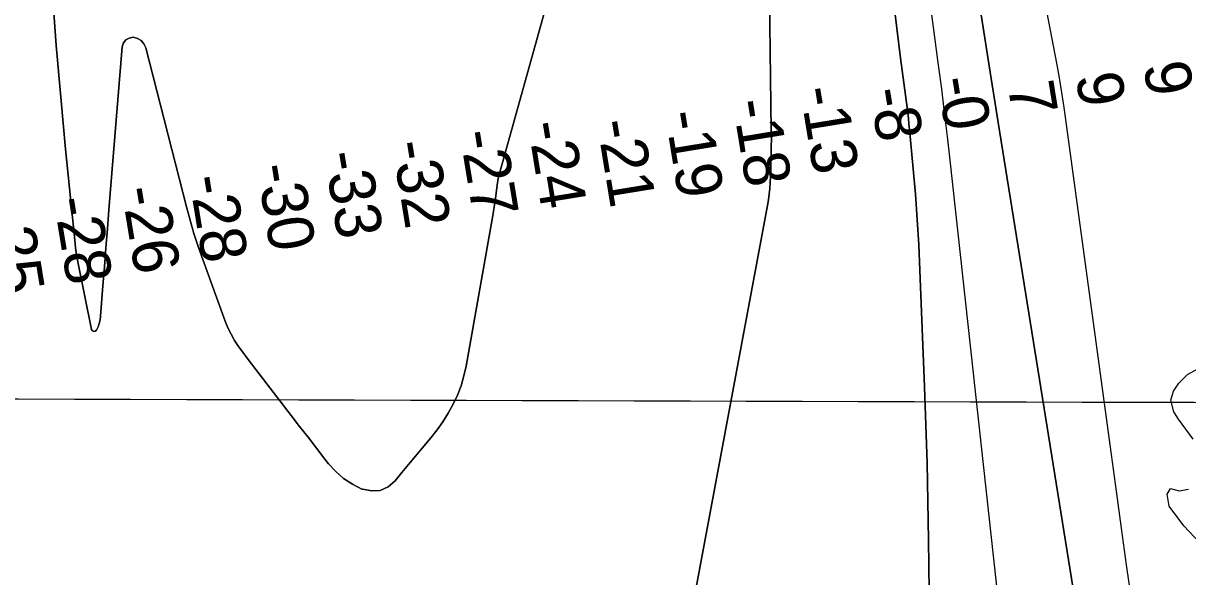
# Model space of a CAD drawing. Extents: x 3161665 to 3199565, y 885729 to 911164.
# Drawn here: x 3176516 to 3178214, y 896967 to 897774 of the extents above; entities that cross this region are included whole.
import ezdxf

# ---------------------------------------------------------------- set-up
doc = ezdxf.new("R2010")
doc.units = 0
for name, color, linetype in [('V-GRID-MAJR', 7, 'Continuous'), ('V-RIVR-EDGE', 7, 'Continuous'), ('V-RIVR-RANG', 7, 'Continuous'), ('V-TOPO-DPTH', 7, 'Continuous'), ('V-TOPO-MINR', 7, 'Continuous')]:
    doc.layers.add(name, color=color, linetype=linetype)

msp = doc.modelspace()

# ---------------------------------------------------------------- linework, layer by layer
at = {"layer": 'V-GRID-MAJR'}
msp.add_spline([(3165896.843, 897258.21), (3171121.2120000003, 897241.873), (3176345.5840000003, 897226.295), (3181569.957, 897211.478), (3186794.333, 897197.42), (3192018.711, 897184.122), (3197243.091, 897171.584), (3197243.092, 897171.584)], degree=3, dxfattribs=at)
at = {"layer": 'V-RIVR-EDGE'}
for points in [[(3178221.800052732, 897167.374816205), (3178200.571841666, 897196.116133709), (3178193.6438879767, 897207.0002441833), (3178189.3390410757, 897223.963377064), (3178193.2833747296, 897236.9939994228), (3178201.1365726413, 897248.7109187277), (3178213.339760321, 897261.7211193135), (3178271.665952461, 897293.7431551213)], [(3178231.857173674, 897015.6469121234), (3178208.4469813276, 897040.9161915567), (3178186.783018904, 897069.2239073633), (3178183.784351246, 897087.0531688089), (3178188.586214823, 897095.300199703), (3178201.617912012, 897091.790542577), (3178215.099333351, 897094.3652820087)]]:
    msp.add_lwpolyline(points, dxfattribs=at)
at = {"layer": 'V-TOPO-DPTH'}
for points in [[(3176558.5467961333, 897817.1781093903), (3176563.9325209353, 897741.495914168), (3176570.356555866, 897665.8947734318), (3176577.4727975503, 897590.3476690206), (3176591.3818922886, 897452.8044901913), (3176592.161481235, 897446.0843880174), (3176593.0721583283, 897439.3840700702), (3176594.1794676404, 897432.7134284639), (3176595.4178651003, 897426.062571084), (3176615.3516896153, 897327.1175453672), (3176616.903670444, 897325.0651113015), (3176618.605038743, 897324.033915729), (3176620.530488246, 897324.5345778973), (3176622.6053252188, 897326.0564785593), (3176624.8307228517, 897330.9478512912), (3176626.6335518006, 897335.9621829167), (3176627.802527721, 897341.1609528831), (3176628.548934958, 897346.4826817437), (3176631.9842188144, 897390.9979992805), (3176634.1354684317, 897418.671701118), (3176636.307454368, 897446.3437636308), (3176638.510544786, 897474.0133671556), (3176640.7343715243, 897501.6813313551), (3176659.9849144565, 897739.514971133), (3176662.011104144, 897745.2858974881), (3176665.1738907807, 897749.7408993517), (3176670.041572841, 897752.2220144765), (3176676.045851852, 897753.3872051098), (3176682.4314041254, 897751.6444726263), (3176687.8172042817, 897748.6977806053), (3176691.7033762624, 897743.9451492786), (3176694.5897961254, 897737.9885584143), (3176753.850988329, 897505.9194578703), (3176759.118354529, 897486.5033590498), (3176764.767142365, 897467.2050996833), (3176770.9880626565, 897448.0835994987), (3176777.590404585, 897429.0799387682), (3176810.2576448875, 897339.3855753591), (3176814.244132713, 897329.6909031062), (3176818.732541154, 897320.2607260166), (3176823.973830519, 897311.2272916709), (3176829.7170404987, 897302.4583524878), (3176835.889227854, 897293.9255698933), (3176842.123683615, 897285.4390635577), (3176848.4515419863, 897277.0219716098), (3176854.841668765, 897268.6511559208), (3176906.4900322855, 897201.7634021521), (3176918.7918004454, 897185.8541747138), (3176931.107930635, 897169.9560890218), (3176943.4456038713, 897154.0747159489), (3176955.797639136, 897138.2044846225), (3176961.084816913, 897131.4208671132), (3176971.5675435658, 897119.9552063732), (3176983.0130185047, 897109.7560533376), (3176995.9026158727, 897101.4566618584), (3177009.7549615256, 897094.4237780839), (3177010.4865470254, 897094.1220271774), (3177023.8712964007, 897091.619790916), (3177036.44042938, 897092.2990701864), (3177047.7861377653, 897097.7506227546), (3177058.316229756, 897106.3836908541), (3177068.0194433, 897118.3605052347), (3177077.7738969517, 897130.2951632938), (3177087.6052107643, 897142.1665868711), (3177097.487764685, 897153.995854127), (3177110.1230216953, 897169.0212029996), (3177119.2508104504, 897180.6517842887), (3177127.8262804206, 897192.6496344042), (3177135.573272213, 897205.1983877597), (3177142.7679452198, 897218.1144099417), (3177148.9085474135, 897231.5229973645), (3177154.2174806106, 897245.2119264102), (3177158.278910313, 897259.3213678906), (3177161.5086710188, 897273.7111509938), (3177200.5150993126, 897493.2873469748), (3177201.062739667, 897496.4032050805), (3177201.602780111, 897499.5203655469), (3177202.1314206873, 897502.639479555), (3177202.6524613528, 897505.7598959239), (3177203.148017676, 897508.8841289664), (3177203.6172047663, 897512.0121471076), (3177204.0468380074, 897515.145842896), (3177204.450102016, 897518.2833237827), (3177205.442649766, 897526.4113099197), (3177206.3350441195, 897533.6140049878), (3177207.2442922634, 897540.814541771), (3177208.1788210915, 897548.0118411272), (3177366.8356769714, 898116.712114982)], [(3177366.8356769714, 898116.712114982), (3177208.1788210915, 897548.0118411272), (3177207.2442922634, 897540.814541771), (3177206.3350441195, 897533.6140049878), (3177205.442649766, 897526.4113099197), (3177204.450102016, 897518.2833237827), (3177204.0468380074, 897515.145842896), (3177203.6172047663, 897512.0121471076), (3177203.148017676, 897508.8841289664), (3177202.6524613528, 897505.7598959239), (3177202.1314206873, 897502.639479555), (3177201.602780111, 897499.5203655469), (3177201.062739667, 897496.4032050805), (3177200.5150993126, 897493.2873469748), (3177161.5086710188, 897273.7111509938), (3177158.278910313, 897259.3213678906), (3177154.2174806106, 897245.2119264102), (3177148.9085474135, 897231.5229973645), (3177142.7679452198, 897218.1144099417), (3177135.573272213, 897205.1983877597), (3177127.8262804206, 897192.6496344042), (3177119.2508104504, 897180.6517842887), (3177110.1230216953, 897169.0212029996), (3177097.487764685, 897153.995854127), (3177087.6052107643, 897142.1665868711), (3177077.7738969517, 897130.2951632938), (3177068.0194433, 897118.3605052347), (3177058.316229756, 897106.3836908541), (3177047.7861377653, 897097.7506227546), (3177036.44042938, 897092.2990701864), (3177023.8712964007, 897091.619790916), (3177010.4865470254, 897094.1220271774), (3177009.7549615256, 897094.4237780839), (3176995.9026158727, 897101.4566618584), (3176983.0130185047, 897109.7560533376), (3176971.5675435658, 897119.9552063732), (3176961.084816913, 897131.4208671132), (3176955.797639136, 897138.2044846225), (3176943.4456038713, 897154.0747159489), (3176931.107930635, 897169.9560890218), (3176918.7918004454, 897185.8541747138), (3176906.4900322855, 897201.7634021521), (3176854.841668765, 897268.6511559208), (3176848.4515419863, 897277.0219716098), (3176842.123683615, 897285.4390635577), (3176835.889227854, 897293.9255698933), (3176829.7170404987, 897302.4583524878), (3176823.973830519, 897311.2272916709), (3176818.732541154, 897320.2607260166), (3176814.244132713, 897329.6909031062), (3176810.2576448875, 897339.3855753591), (3176777.590404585, 897429.0799387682), (3176770.9880626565, 897448.0835994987), (3176764.767142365, 897467.2050996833), (3176759.118354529, 897486.5033590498), (3176753.850988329, 897505.9194578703), (3176694.5897961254, 897737.9885584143), (3176691.7033762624, 897743.9451492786), (3176687.8172042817, 897748.6977806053), (3176682.4314041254, 897751.6444726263), (3176676.045851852, 897753.3872051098), (3176670.041572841, 897752.2220144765), (3176665.1738907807, 897749.7408993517), (3176662.011104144, 897745.2858974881), (3176659.9849144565, 897739.514971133), (3176640.7343715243, 897501.6813313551), (3176638.510544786, 897474.0133671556), (3176636.307454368, 897446.3437636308), (3176634.1354684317, 897418.671701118), (3176631.9842188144, 897390.9979992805), (3176628.548934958, 897346.4826817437), (3176627.802527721, 897341.1609528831), (3176626.6335518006, 897335.9621829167), (3176624.8307228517, 897330.9478512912), (3176622.6053252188, 897326.0564785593), (3176620.530488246, 897324.5345778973), (3176618.605038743, 897324.033915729), (3176616.903670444, 897325.0651113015), (3176615.3516896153, 897327.1175453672), (3176595.4178651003, 897426.062571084), (3176594.1794676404, 897432.7134284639), (3176593.0721583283, 897439.3840700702), (3176592.161481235, 897446.0843880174), (3176591.3818922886, 897452.8044901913), (3176577.4727975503, 897590.3476690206), (3176570.356555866, 897665.8947734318), (3176563.9325209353, 897741.495914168), (3176558.5467961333, 897817.1781093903)], [(3177494.1782761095, 896935.1771381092), (3177600.946914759, 897508.1896997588), (3177602.339676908, 897516.414515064), (3177603.5148476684, 897524.6806495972), (3177604.400248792, 897532.9868447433), (3177605.1180357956, 897541.3049577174), (3177605.5844016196, 897549.6409474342), (3177605.8831533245, 897557.9888549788), (3177606.528392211, 897589.1979617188), (3177606.6352435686, 897596.0085103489), (3177606.6968362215, 897602.8192427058), (3177606.690540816, 897609.6302506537), (3177606.6389867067, 897616.4414423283), (3177600.774823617, 898083.5755915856)], [(3177600.774823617, 898083.5755915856), (3177606.6389867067, 897616.4414423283), (3177606.690540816, 897609.6302506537), (3177606.6968362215, 897602.8192427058), (3177606.6352435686, 897596.0085103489), (3177606.528392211, 897589.1979617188), (3177605.8831533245, 897557.9888549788), (3177605.5844016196, 897549.6409474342), (3177605.1180357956, 897541.3049577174), (3177604.400248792, 897532.9868447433), (3177603.5148476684, 897524.6806495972), (3177602.339676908, 897516.414515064), (3177600.946914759, 897508.1896997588), (3177494.1782761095, 896935.1771381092)], [(3178046.6456379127, 896948.8952665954), (3177941.9240149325, 897601.6069131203), (3177937.528139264, 897629.1094230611), (3177933.153914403, 897656.6153629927), (3177928.812165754, 897684.1264479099), (3177924.4920679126, 897711.640962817), (3177904.0084826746, 897842.604480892)], [(3177904.0084826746, 897842.604480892), (3177924.4920679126, 897711.640962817), (3177928.812165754, 897684.1264479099), (3177933.153914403, 897656.6153629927), (3177937.528139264, 897629.1094230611), (3177941.9240149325, 897601.6069131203), (3178046.6456379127, 896948.8952665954)], [(3177784.425651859, 897810.8513964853), (3177789.702582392, 897766.8668961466), (3177795.2276850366, 897722.911105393), (3177804.5818895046, 897650.9532852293), (3177805.5739509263, 897642.993219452), (3177806.509894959, 897635.0268608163), (3177807.3616629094, 897627.0510628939), (3177808.1573134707, 897619.0689721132), (3177813.6078454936, 897561.2993788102), (3177816.7813359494, 897524.4074245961), (3177819.547980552, 897487.4883596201), (3177821.7043563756, 897450.5286285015), (3177823.453886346, 897413.5417866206), (3177830.0906132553, 897243.4779937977), (3177832.045480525, 897187.7502965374), (3177833.707483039, 897132.0150211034), (3177834.930188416, 897076.2683784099), (3177835.860029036, 897020.5141575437), (3177836.3474722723, 896982.241415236), (3177836.7100848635, 896945.6175398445)], [(3177784.425651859, 897810.8513964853), (3177789.702582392, 897766.8668961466), (3177795.2276850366, 897722.911105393), (3177804.5818895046, 897650.9532852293), (3177805.5739509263, 897642.993219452), (3177806.509894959, 897635.0268608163), (3177807.3616629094, 897627.0510628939), (3177808.1573134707, 897619.0689721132), (3177813.6078454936, 897561.2993788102), (3177816.7813359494, 897524.4074245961), (3177819.547980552, 897487.4883596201), (3177821.7043563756, 897450.5286285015), (3177823.453886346, 897413.5417866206), (3177830.0906132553, 897243.4779937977), (3177832.045480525, 897187.7502965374), (3177833.707483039, 897132.0150211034), (3177834.930188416, 897076.2683784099), (3177835.860029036, 897020.5141575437), (3177836.3474722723, 896982.241415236), (3177836.7100848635, 896945.6175398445)]]:
    msp.add_lwpolyline(points, dxfattribs=at)
at = {"layer": 'V-TOPO-MINR'}
for points in [[(3177976.697404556, 895952.0490213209), (3177973.571543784, 896154.3247767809), (3177971.4807912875, 896258.129303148), (3177968.741664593, 896361.9136764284), (3177965.0299766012, 896465.667820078), (3177960.6699144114, 896569.4018106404), (3177953.302895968, 896727.0636358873), (3177951.8041204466, 896755.9112628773), (3177950.104902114, 896784.7460285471), (3177948.105019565, 896813.5615022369), (3177945.904694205, 896842.3641146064), (3177943.4350937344, 896871.1457194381), (3177940.806978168, 896899.9121811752), (3177937.941089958, 896928.6559282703), (3177934.9166866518, 896957.3845322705), (3177867.408542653, 897574.1384832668), (3177863.4913699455, 897608.8594609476), (3177859.420624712, 897643.5619067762), (3177855.119520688, 897678.2365548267), (3177850.664844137, 897712.8926710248), (3177768.305226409, 898337.2257683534)], [(3176558.5467961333, 897817.1781093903), (3176563.9325209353, 897741.495914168), (3176570.356555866, 897665.8947734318), (3176577.4727975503, 897590.3476690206), (3176591.3818922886, 897452.8044901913), (3176592.161481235, 897446.0843880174), (3176593.0721583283, 897439.3840700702), (3176594.1794676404, 897432.7134284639), (3176595.4178651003, 897426.062571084), (3176615.3516896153, 897327.1175453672), (3176616.903670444, 897325.0651113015), (3176618.605038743, 897324.033915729), (3176620.530488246, 897324.5345778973), (3176622.6053252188, 897326.0564785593), (3176624.8307228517, 897330.9478512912), (3176626.6335518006, 897335.9621829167), (3176627.802527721, 897341.1609528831), (3176628.548934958, 897346.4826817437), (3176631.9842188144, 897390.9979992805), (3176634.1354684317, 897418.671701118), (3176636.307454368, 897446.3437636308), (3176638.510544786, 897474.0133671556), (3176640.7343715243, 897501.6813313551), (3176659.9849144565, 897739.514971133), (3176662.011104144, 897745.2858974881), (3176665.1738907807, 897749.7408993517), (3176670.041572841, 897752.2220144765), (3176676.045851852, 897753.3872051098), (3176682.4314041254, 897751.6444726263), (3176687.8172042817, 897748.6977806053), (3176691.7033762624, 897743.9451492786), (3176694.5897961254, 897737.9885584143), (3176753.850988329, 897505.9194578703), (3176759.118354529, 897486.5033590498), (3176764.767142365, 897467.2050996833), (3176770.9880626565, 897448.0835994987), (3176777.590404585, 897429.0799387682), (3176810.2576448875, 897339.3855753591), (3176814.244132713, 897329.6909031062), (3176818.732541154, 897320.2607260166), (3176823.973830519, 897311.2272916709), (3176829.7170404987, 897302.4583524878), (3176835.889227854, 897293.9255698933), (3176842.123683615, 897285.4390635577), (3176848.4515419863, 897277.0219716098), (3176854.841668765, 897268.6511559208), (3176906.4900322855, 897201.7634021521), (3176918.7918004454, 897185.8541747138), (3176931.107930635, 897169.9560890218), (3176943.4456038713, 897154.0747159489), (3176955.797639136, 897138.2044846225), (3176961.084816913, 897131.4208671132), (3176971.5675435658, 897119.9552063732), (3176983.0130185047, 897109.7560533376), (3176995.9026158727, 897101.4566618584), (3177009.7549615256, 897094.4237780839), (3177010.4865470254, 897094.1220271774), (3177023.8712964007, 897091.619790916), (3177036.44042938, 897092.2990701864), (3177047.7861377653, 897097.7506227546), (3177058.316229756, 897106.3836908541), (3177068.0194433, 897118.3605052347), (3177077.7738969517, 897130.2951632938), (3177087.6052107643, 897142.1665868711), (3177097.487764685, 897153.995854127), (3177110.1230216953, 897169.0212029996), (3177119.2508104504, 897180.6517842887), (3177127.8262804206, 897192.6496344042), (3177135.573272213, 897205.1983877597), (3177142.7679452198, 897218.1144099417), (3177148.9085474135, 897231.5229973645), (3177154.2174806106, 897245.2119264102), (3177158.278910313, 897259.3213678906), (3177161.5086710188, 897273.7111509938), (3177200.5150993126, 897493.2873469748), (3177201.062739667, 897496.4032050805), (3177201.602780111, 897499.5203655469), (3177202.1314206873, 897502.639479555), (3177202.6524613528, 897505.7598959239), (3177203.148017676, 897508.8841289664), (3177203.6172047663, 897512.0121471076), (3177204.0468380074, 897515.145842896), (3177204.450102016, 897518.2833237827), (3177205.442649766, 897526.4113099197), (3177206.3350441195, 897533.6140049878), (3177207.2442922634, 897540.814541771), (3177208.1788210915, 897548.0118411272), (3177366.8356769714, 898116.712114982)], [(3177600.774823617, 898083.5755915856), (3177606.6389867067, 897616.4414423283), (3177606.690540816, 897609.6302506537), (3177606.6968362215, 897602.8192427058), (3177606.6352435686, 897596.0085103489), (3177606.528392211, 897589.1979617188), (3177605.8831533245, 897557.9888549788), (3177605.5844016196, 897549.6409474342), (3177605.1180357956, 897541.3049577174), (3177604.400248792, 897532.9868447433), (3177603.5148476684, 897524.6806495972), (3177602.339676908, 897516.414515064), (3177600.946914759, 897508.1896997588), (3177494.1782761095, 896935.1771381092)], [(3178046.6456379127, 896948.8952665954), (3177941.9240149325, 897601.6069131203), (3177937.528139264, 897629.1094230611), (3177933.153914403, 897656.6153629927), (3177928.812165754, 897684.1264479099), (3177924.4920679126, 897711.640962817), (3177904.0084826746, 897842.604480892)], [(3177836.7100848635, 896945.6175398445), (3177836.3474722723, 896982.241415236), (3177835.860029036, 897020.5141575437), (3177834.930188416, 897076.2683784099), (3177833.707483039, 897132.0150211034), (3177832.045480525, 897187.7502965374), (3177830.0906132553, 897243.4779937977), (3177823.453886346, 897413.5417866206), (3177821.7043563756, 897450.5286285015), (3177819.547980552, 897487.4883596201), (3177816.7813359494, 897524.4074245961), (3177813.6078454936, 897561.2993788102), (3177808.1573134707, 897619.0689721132), (3177807.3616629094, 897627.0510628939), (3177806.509894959, 897635.0268608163), (3177805.5739509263, 897642.993219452), (3177804.5818895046, 897650.9532852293), (3177795.2276850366, 897722.911105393), (3177789.702582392, 897766.8668961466), (3177784.425651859, 897810.8513964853)], [(3178248.9397078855, 896140.1080694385), (3178149.456821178, 896809.9864307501), (3178148.4826740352, 896816.5907544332), (3178147.51721106, 896823.1963386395), (3178146.5647743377, 896829.8038136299), (3178145.621021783, 896836.4125491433), (3178132.297540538, 896930.3735611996), (3178124.7462508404, 896983.9703663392), (3178117.2585477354, 897037.5759956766), (3178109.8662245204, 897091.194861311), (3178102.537487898, 897144.8225511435), (3178036.7172564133, 897629.6735479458), (3178033.628216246, 897651.1601703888), (3178030.3147190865, 897672.6103118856), (3178026.664536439, 897694.0057319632), (3178022.789896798, 897715.3646710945), (3178003.9703778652, 897814.6577553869)]]:
    msp.add_lwpolyline(points, dxfattribs=at)

# ---------------------------------------------------------------- texts
at = {"layer": 'V-RIVR-RANG'}
for s, p in [('9', (3178148.9863444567, 897713.1271327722)), ('-0', (3177848.3780553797, 897692.4496155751)), ('7', (3177951.067438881, 897684.1575684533)), ('9', (3178050.261344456, 897697.2101327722)), ('-13', (3177648.071994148, 897678.0565419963)), ('-8', (3177749.6956831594, 897676.2723032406)), ('-18', (3177549.7732719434, 897659.53641865)), ('-19', (3177451.175155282, 897642.8394816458)), ('-24', (3177250.996977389, 897627.6654710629)), ('-21', (3177351.938621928, 897630.0462296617)), ('-27', (3177151.8030718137, 897614.6119067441)), ('-32', (3177052.9928162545, 897599.2155314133)), ('-33', (3176954.1825606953, 897583.8201560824)), ('-30', (3176855.8402107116, 897565.5603450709)), ('-28', (3176757.2430940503, 897548.862408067)), ('-26', (3176658.6033496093, 897532.4247833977)), ('-25', (3176460.897582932, 897502.1536574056)), ('-28', (3176559.793094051, 897517.028408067))]:
    msp.add_text(s, height=66.99999999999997, rotation=279.3, dxfattribs=at).set_placement(p)

doc.saveas('drawing.dxf')
